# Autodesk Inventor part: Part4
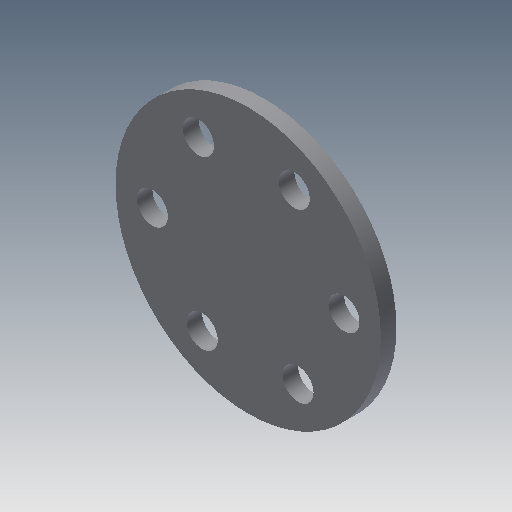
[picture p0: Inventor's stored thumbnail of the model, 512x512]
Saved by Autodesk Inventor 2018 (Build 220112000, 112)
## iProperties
Created: 2008-05
Part Number: Part4
Document SubType Name: Modeling
Designer: CADCIM
Density: 1 g/cm^3
Material: Generic
Appearance: Default
Author: CADCIM
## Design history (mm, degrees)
sketch "Sketch1"
  geometry: C1 r 17 at (0, 0)
  constraints: 1 centre point, 1 other
  dimensions: "d12" = 34 diameter of C1
extrude "Extrusion1" new body sketch "Sketch1" distance "d0" = 2; taper "d1" = 0 deg
sketch "Sketch2"
  geometry: 1 further point
hole "Hole1" sketch "Sketch2" at (5.9, 10.769) diameter "d2" = 4; stored, may be unused: countersink angle "d6" = 90 deg, drill point angle "d8" = 118 deg; dims "d3" = 6, "d4" = 4, "d5" = 2, "d7" = 8
pattern_circular "Circular Pattern1" dims angle "d10" = 360 deg
body "Solid1"
